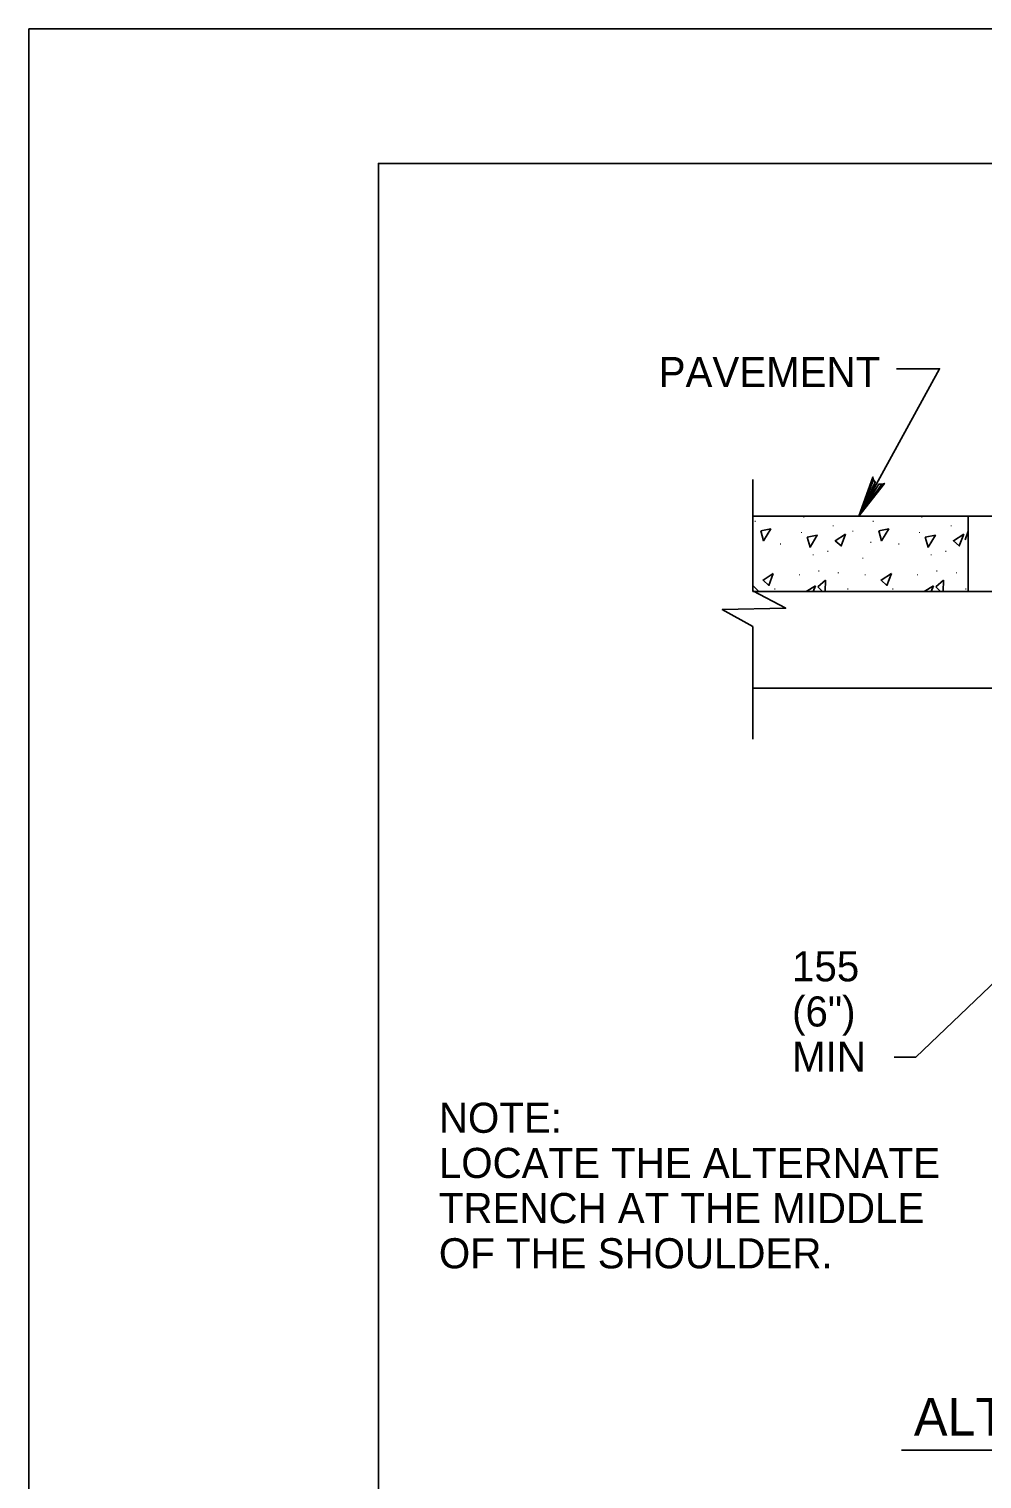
# Model space of a CAD drawing. Extents: x 638448 to 639352, y 297825 to 299013.
# Drawn here: x 638447.7 to 638554, y 298851.5 to 299013.3 of the extents above; entities that cross this region are included whole.
import ezdxf

# ---------------------------------------------------------------- set-up
doc = ezdxf.new("R2010")
doc.units = 0
for name, color, linetype in [('1', 7, 'Continuous'), ('2', 7, 'Continuous'), ('3', 7, 'Continuous'), ('PLT-BNDY', 7, 'Continuous')]:
    doc.layers.add(name, color=color, linetype=linetype)

msp = doc.modelspace()

# ---------------------------------------------------------------- linework, layer by layer
at = {"layer": '1'}
msp.add_lwpolyline([(639272.65, 298434.29), (639272.65, 298998.29), (638486.65, 298998.29), (638486.65, 298434.29), (639272.65, 298434.29), (639272.65, 298460.65), (639072.65, 298460.65), (639072.65, 298525.33), (639272.65, 298525.33), (639272.65, 298554.29), (639072.65, 298554.29), (639072.65, 298434.29), (639151.45, 298434.29), (639151.45, 298460.65), (639151.45, 298434.29), (639228.45, 298434.29), (639228.45, 298460.65), (639228.45, 298448.33), (639272.65, 298448.33)], dxfattribs=at)
at = {"layer": '2'}
for p, q in [((638528.44, 298963.04), (638528.44, 298950.61)), ((638528.44, 298958.93), (638552.44, 298958.93)), ((638552.44, 298958.93), (638552.44, 298950.53)), ((638552.44, 298958.93), (638612.25, 298958.93)), ((638552.44, 298950.53), (638528.44, 298950.53)), ((638552.44, 298950.53), (638612.25, 298950.53)), ((638528.44, 298946.61), (638528.44, 298934.05)), ((638552.44, 298939.73), (638528.44, 298939.73)), ((638552.44, 298939.73), (638612.25, 298939.73))]:
    msp.add_line(p, q, dxfattribs=at)
for points in [[(638544.47, 298975.38), (638549.27, 298975.38), (638540.26, 298958.93)], [(638542.83, 298962.49), (638542.48, 298962.5), (638540.26, 298958.93), (638542.83, 298962.49), (638543.11, 298962.59), (638540.26, 298958.93), (638542.09, 298962.71), (638541.89, 298962.99), (638540.26, 298958.93), (638541.82, 298963.3), (638541.89, 298962.99)], [(638552.44, 298957.24), (638552.13, 298956.3)], [(638535.66, 298951.04), (638536.52, 298951.79)], [(638536.52, 298951.79), (638536.49, 298950.53)], [(638548.83, 298951.04), (638549.69, 298951.79)], [(638549.69, 298951.79), (638549.66, 298950.53)], [(638528.44, 298950.61), (638532.09, 298948.66), (638525.02, 298948.52), (638528.44, 298946.61)], [(638529.1, 298950.53), (638528.44, 298951.19)], [(638535.41, 298951.16), (638534.39, 298950.53)], [(638535.16, 298950.53), (638535.41, 298951.16)], [(638536.18, 298950.53), (638535.66, 298951.04)], [(638548.58, 298951.16), (638547.56, 298950.53)], [(638548.33, 298950.53), (638548.58, 298951.16)], [(638549.35, 298950.53), (638548.83, 298951.04)], [(638544.2, 298898.57), (638546.6, 298898.57), (638558.19, 298909.62)]]:
    msp.add_lwpolyline(points, dxfattribs=at)
for points in [[(638528.44, 298958.93), (638552.44, 298958.93), (638552.44, 298950.53), (638528.44, 298950.53)], [(638529.31, 298957.29), (638530.43, 298957.51), (638529.63, 298956.18)], [(638534.49, 298956.58), (638535.62, 298956.8), (638534.81, 298955.46)], [(638538.78, 298956.91), (638537.63, 298956.19), (638538.29, 298955.61)], [(638542.48, 298957.29), (638543.6, 298957.51), (638542.8, 298956.18)], [(638547.66, 298956.58), (638548.79, 298956.8), (638547.98, 298955.46)], [(638551.96, 298956.91), (638550.8, 298956.19), (638551.46, 298955.61)], [(638530.71, 298952.52), (638529.56, 298951.8), (638530.21, 298951.21)], [(638543.88, 298952.52), (638542.73, 298951.8), (638543.38, 298951.21)]]:
    msp.add_lwpolyline(points, close=True, dxfattribs=at)
at = {"layer": '3'}
msp.add_line((638545.02, 298854.72), (638625.44, 298854.72), dxfattribs=at)
at = {"layer": 'PLT-BNDY'}
msp.add_lwpolyline([(638447.65, 299013.29), (639288.65, 299013.29), (639288.65, 298419.29), (638447.65, 298419.29)], close=True, dxfattribs=at)

# ---------------------------------------------------------------- texts
at = {"layer": '1'}
for s, p in [('NOTE:', (638493.39, 298890.13)), ('LOCATE THE ALTERNATE', (638493.39, 298885.09)), ('TRENCH AT THE MIDDLE', (638493.39, 298880.05)), ('OF THE SHOULDER.', (638493.39, 298875.01))]:
    msp.add_text(s, height=3.36, dxfattribs=at).set_placement(p)
at = {"layer": '2'}
for p in [(638528.53, 298958.28), (638533.94, 298958.75), (638541.7, 298958.28), (638547.11, 298958.75), (638533.69, 298957.04), (638533.69, 298957.04), (638537.23, 298957.78), (638539.4, 298957.19), (638546.86, 298957.04), (638546.86, 298957.04), (638550.4, 298957.78), (638531.36, 298955.76), (638536.62, 298954.95), (638541.43, 298955.94), (638544.54, 298955.76), (638549.79, 298954.95), (638534.99, 298954.55), (638540.52, 298954.18), (638548.16, 298954.55), (638533.48, 298952.32), (638535.62, 298952.75), (638537.8, 298952.54), (638540.81, 298952.32), (638546.65, 298952.32), (638548.79, 298952.75), (638550.97, 298952.54), (638530.71, 298950.73), (638538.85, 298950.73), (638543.88, 298950.73), (638552.02, 298950.73)]:
    msp.add_text('.', height=0.893, dxfattribs=at).set_placement(p)
at = {"layer": '3'}
for s, height, p in [('PAVEMENT', 3.36, (638517.92, 298973.33)), ('155', 3.36, (638532.8, 298907.03)), ('(6")', 3.36, (638532.8, 298901.99)), ('MIN', 3.36, (638532.8, 298896.95)), ('ALTERNATE TREATMENT', 4.2, (638546.4, 298856.35))]:
    msp.add_text(s, height=height, dxfattribs=at).set_placement(p)

doc.saveas('drawing.dxf')
